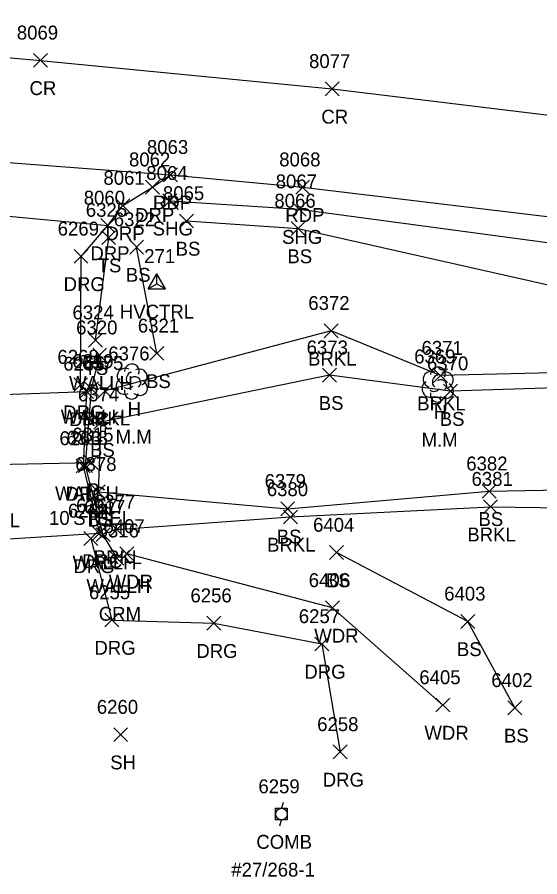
# Model space of a CAD drawing. Extents: x 1588028 to 1589597, y 137576 to 138176.
# Drawn here: x 1588699 to 1588774.4, y 137773.7 to 137897.5 of the extents above; entities that cross this region are included whole.
import ezdxf

# ---------------------------------------------------------------- set-up
doc = ezdxf.new("R2010")
doc.units = 0
for name, color, linetype in [('C_A', 7, 'Continuous'), ('C_I', 7, 'Continuous'), ('CPSM', 7, 'Continuous'), ('D_A', 7, 'Continuous'), ('D_C', 7, 'Continuous'), ('D_I', 7, 'Continuous'), ('D_TIC', 7, 'Continuous'), ('DCP', 7, 'Continuous'), ('DHW', 7, 'Continuous'), ('L_A', 7, 'Continuous'), ('L_C', 7, 'Continuous'), ('L_I', 7, 'Continuous'), ('L_TIC', 7, 'Continuous'), ('LAWA', 7, 'Continuous'), ('LAWE', 7, 'Continuous'), ('LELB', 7, 'Continuous'), ('LTD', 7, 'Continuous'), ('P_A', 7, 'Continuous'), ('P_I', 7, 'Continuous'), ('P_TIC', 7, 'Continuous'), ('PET', 7, 'Continuous'), ('PRC', 7, 'Continuous'), ('PSU', 7, 'Continuous'), ('R_A', 7, 'Continuous'), ('R_I', 7, 'Continuous'), ('R_TIC', 7, 'Continuous'), ('RDG', 7, 'Continuous'), ('RDP', 7, 'Continuous'), ('U_A', 7, 'Continuous'), ('U_C', 7, 'Continuous'), ('U_I', 7, 'Continuous'), ('UP', 7, 'Continuous')]:
    doc.layers.add(name, color=color, linetype=linetype)

msp = doc.modelspace()

# ---------------------------------------------------------------- linework, layer by layer
at = {"layer": 'CPSM'}
for p, q in [((1588717.9, 137858.35), (1588719.15, 137860.52)), ((1588720.4, 137858.35), (1588719.15, 137860.52)), ((1588719.15, 137859.07), (1588719.15, 137860.52)), ((1588717.9, 137858.35), (1588719.15, 137859.07)), ((1588719.15, 137859.07), (1588719.15, 137859.07)), ((1588719.15, 137859.07), (1588720.4, 137858.35)), ((1588717.9, 137858.35), (1588720.4, 137858.35))]:
    msp.add_line(p, q, dxfattribs=at)
at = {"layer": 'D_TIC'}
for points in [[(1588709.93, 137847.79), (1588711.93, 137849.79)], [(1588711.93, 137847.79), (1588709.93, 137849.79)], [(1588708.74, 137842.94), (1588710.74, 137844.94)], [(1588710.74, 137842.94), (1588708.74, 137844.94)], [(1588707.9, 137831.91), (1588709.9, 137833.91)], [(1588709.9, 137831.91), (1588707.9, 137833.91)], [(1588708.71, 137832.36), (1588710.71, 137834.36)], [(1588710.71, 137832.36), (1588708.71, 137834.36)], [(1588710.43, 137821.95), (1588712.43, 137823.95)], [(1588712.43, 137821.95), (1588710.43, 137823.95)], [(1588712.43, 137818.55), (1588714.43, 137820.55)], [(1588714.43, 137818.55), (1588712.43, 137820.55)]]:
    msp.add_lwpolyline(points, dxfattribs=at)
at = {"layer": 'DCP'}
msp.add_lwpolyline([(1588693.57, 137833.03), (1588709.71, 137833.36)], dxfattribs=at)
at = {"layer": 'DHW'}
msp.add_lwpolyline([(1588713.43, 137819.55), (1588711.43, 137822.95), (1588708.9, 137832.91), (1588709.74, 137843.94), (1588710.93, 137848.79)], dxfattribs=at)
at = {"layer": 'L_TIC'}
for points in [[(1588722.44, 137867.13), (1588724.44, 137869.13)], [(1588724.44, 137867.13), (1588722.44, 137869.13)], [(1588738.55, 137866.04), (1588740.55, 137868.04)], [(1588740.55, 137866.04), (1588738.55, 137868.04)], [(1588711.23, 137864.73), (1588713.23, 137866.73)], [(1588713.23, 137864.73), (1588711.23, 137866.73)], [(1588715.26, 137863.37), (1588717.26, 137865.37)], [(1588717.26, 137863.37), (1588715.26, 137865.37)], [(1588743.31, 137851.31), (1588745.31, 137853.31)], [(1588745.31, 137851.31), (1588743.31, 137853.31)], [(1588709.32, 137849.96), (1588711.32, 137851.96)], [(1588711.32, 137849.96), (1588709.32, 137851.96)], [(1588718.17, 137848.06), (1588720.17, 137850.06)], [(1588720.17, 137848.06), (1588718.17, 137850.06)], [(1588743.06, 137844.91), (1588745.06, 137846.91)], [(1588745.06, 137844.91), (1588743.06, 137846.91)], [(1588759.06, 137844.85), (1588761.06, 137846.85)], [(1588761.06, 137844.85), (1588759.06, 137846.85)], [(1588710.69, 137842.68), (1588712.69, 137844.68)], [(1588712.69, 137842.68), (1588710.69, 137844.68)], [(1588760.5, 137842.62), (1588762.5, 137844.62)], [(1588762.5, 137842.62), (1588760.5, 137844.62)], [(1588710.1, 137838.15), (1588712.1, 137840.15)], [(1588712.1, 137838.15), (1588710.1, 137840.15)], [(1588709.72, 137828.12), (1588711.72, 137830.12)], [(1588711.72, 137828.12), (1588709.72, 137830.12)], [(1588766.07, 137828.2), (1588768.07, 137830.2)], [(1588768.07, 137828.2), (1588766.07, 137830.2)], [(1588737.02, 137825.67), (1588739.02, 137827.67)], [(1588739.02, 137825.67), (1588737.02, 137827.67)], [(1588766.27, 137825.98), (1588768.27, 137827.98)], [(1588768.27, 137825.98), (1588766.27, 137827.98)], [(1588737.42, 137824.5), (1588739.42, 137826.5)], [(1588739.42, 137824.5), (1588737.42, 137826.5)], [(1588712.41, 137822.71), (1588714.41, 137824.71)], [(1588714.41, 137822.71), (1588712.41, 137824.71)], [(1588713.86, 137819.18), (1588715.86, 137821.18)], [(1588715.86, 137819.18), (1588713.86, 137821.18)], [(1588744.08, 137819.37), (1588746.08, 137821.37)], [(1588746.08, 137819.37), (1588744.08, 137821.37)], [(1588743.5, 137811.4), (1588745.5, 137813.4)], [(1588745.5, 137811.4), (1588743.5, 137813.4)], [(1588762.98, 137809.46), (1588764.98, 137811.46)], [(1588764.98, 137809.46), (1588762.98, 137811.46)], [(1588759.38, 137797.42), (1588761.38, 137799.42)], [(1588761.38, 137797.42), (1588759.38, 137799.42)], [(1588769.76, 137797), (1588771.76, 137799)], [(1588771.76, 137797), (1588769.76, 137799)], [(1588712.96, 137793.15), (1588714.96, 137795.15)], [(1588714.96, 137793.15), (1588712.96, 137795.15)]]:
    msp.add_lwpolyline(points, dxfattribs=at)
at = {"layer": 'LAWA'}
msp.add_lwpolyline([(1588760.38, 137798.42), (1588744.5, 137812.4), (1588714.86, 137820.18)], dxfattribs=at)
at = {"layer": 'LAWE'}
for points in [[(1588977.09, 137801.88), (1588949.99, 137800.55), (1588913.53, 137816.71), (1588888.44, 137827.65), (1588864.1, 137841.15), (1588838.93, 137847.71), (1588814.53, 137847.16), (1588788.4, 137846.57), (1588760.06, 137845.85), (1588744.31, 137852.31), (1588711.69, 137843.68)], [(1588713.41, 137823.71), (1588738.42, 137825.5), (1588767.27, 137826.98), (1588799.24, 137826.53), (1588827.86, 137827.03), (1588853.9, 137816.5), (1588892.67, 137800.6), (1588920.93, 137790.22), (1588953.81, 137785.34), (1588994.96, 137778.72)]]:
    msp.add_lwpolyline(points, dxfattribs=at)
at = {"layer": 'LELB'}
for points in [[(1588723.44, 137868.13), (1588739.55, 137867.04), (1588779.84, 137857.95)], [(1588710.32, 137850.96), (1588712.23, 137865.73)], [(1588719.17, 137849.06), (1588716.26, 137864.37)], [(1588976.95, 137800.76), (1588950.62, 137796.9), (1588914.44, 137812.1), (1588887.83, 137826.14), (1588862.59, 137838.68), (1588839.41, 137844.48), (1588814.28, 137844.58), (1588790.42, 137844.54), (1588761.5, 137843.62), (1588744.06, 137845.91), (1588711.1, 137839.15), (1588710.72, 137829.12), (1588738.02, 137826.67), (1588767.07, 137829.2), (1588800.85, 137829.84), (1588826.76, 137827.94), (1588856.44, 137818.62), (1588893.47, 137804.61), (1588923.15, 137792.66), (1588953.98, 137786.08), (1588988.16, 137786.33)], [(1588770.76, 137798), (1588763.98, 137810.46), (1588745.08, 137820.37)]]:
    msp.add_lwpolyline(points, dxfattribs=at)
at = {"layer": 'LTD'}
for p, q in [((1588715.53, 137845.05), (1588715.53, 137845.05)), ((1588715.53, 137845.05), (1588715.53, 137845.05)), ((1588759.63, 137844.62), (1588759.63, 137844.62)), ((1588759.63, 137844.62), (1588759.63, 137844.62))]:
    msp.add_line(p, q, dxfattribs=at)
for centre in [(1588715.58, 137846.48), (1588759.68, 137846.05)]:
    msp.add_arc(centre, 1.05, 335.5272, 180.9563, dxfattribs=at)
for centre, major_axis, ratio, start_param, end_param in [((1588714.74, 137845.72), (1.21, -0.51), 0.895232, 1.570796, 4.712389), ((1588715.32, 137845.51), (-0.208, -0.792), 0.645439, 3.141593, 6.283185), ((1588716.57, 137845.63), (-1.14, -0.48), 0.949671, 1.570796, 4.712389), ((1588758.84, 137845.28), (1.21, -0.51), 0.895232, 1.570796, 4.712389), ((1588760.68, 137845.2), (-1.14, -0.48), 0.949671, 1.570796, 4.712389), ((1588714.45, 137844.34), (0.58, -1.04), 0.959034, 3.141593, 6.283185), ((1588716.03, 137844.88), (-0.5, 0.667), 0.989748, 3.141593, 6.283185), ((1588716.53, 137844.22), (-1.09, 0.79), 0.841452, 1.570796, 4.712389), ((1588758.55, 137843.91), (0.58, -1.04), 0.959034, 3.141593, 6.283185), ((1588759.43, 137845.07), (-0.208, -0.792), 0.645439, 3.141593, 6.283185), ((1588760.13, 137844.45), (-0.5, 0.667), 0.989748, 3.141593, 6.283185), ((1588715.53, 137843.55), (0.26, 1.06), 0.942809, 1.570796, 4.712389), ((1588715.07, 137844.3), (-0.625, -0.083), 0.423636, 0, 3.141593), ((1588759.18, 137843.87), (-0.625, -0.083), 0.423636, 0, 3.141593), ((1588760.63, 137843.78), (-1.09, 0.79), 0.841452, 1.570796, 4.712389), ((1588759.63, 137843.12), (0.26, 1.06), 0.942809, 1.570796, 4.712389)]:
    msp.add_ellipse(centre, major_axis=major_axis, ratio=ratio, start_param=start_param, end_param=end_param, dxfattribs=at)
at = {"layer": 'P_TIC'}
for points in [[(1588701.39, 137890.26), (1588703.39, 137892.26)], [(1588703.39, 137890.26), (1588701.39, 137892.26)], [(1588743.44, 137886.15), (1588745.44, 137888.15)], [(1588745.44, 137886.15), (1588743.44, 137888.15)], [(1588720.13, 137873.78), (1588722.13, 137875.78)], [(1588722.13, 137873.78), (1588720.13, 137875.78)], [(1588739.19, 137871.99), (1588741.19, 137873.99)], [(1588741.19, 137871.99), (1588739.19, 137873.99)], [(1588720.03, 137870.04), (1588722.03, 137872.04)], [(1588722.03, 137870.04), (1588720.03, 137872.04)], [(1588738.68, 137868.83), (1588740.68, 137870.83)], [(1588740.68, 137868.83), (1588738.68, 137870.83)]]:
    msp.add_lwpolyline(points, dxfattribs=at)
at = {"layer": 'PET'}
msp.add_lwpolyline([(1588419.97, 137892.51), (1588466.09, 137889.91), (1588506.76, 137888.01), (1588548, 137885.78), (1588590.45, 137883.61), (1588638.45, 137880.69), (1588661.69, 137879.38), (1588677.51, 137878.09), (1588721.13, 137874.78), (1588740.19, 137872.99), (1588782.63, 137867.93), (1588820.21, 137862.87), (1588860.26, 137857.26), (1588914.01, 137849.9), (1588927.99, 137847.51)], dxfattribs=at)
at = {"layer": 'PRC'}
msp.add_lwpolyline([(1588420.99, 137907.2), (1588467.18, 137904.92), (1588507.29, 137903.21), (1588549.37, 137901.19), (1588590.55, 137899.3), (1588641.57, 137896.1), (1588661.53, 137894.88), (1588702.39, 137891.26), (1588744.44, 137887.15), (1588784.4, 137882.3), (1588823.71, 137877.3), (1588862.06, 137871.74), (1588917.24, 137863.85)], dxfattribs=at)
at = {"layer": 'PSU'}
msp.add_lwpolyline([(1588721.03, 137871.04), (1588739.68, 137869.83), (1588782.24, 137864.13), (1588819.87, 137858.36), (1588840.12, 137856.16)], dxfattribs=at)
at = {"layer": 'R_TIC'}
for points in [[(1588720.13, 137873.78), (1588722.13, 137875.78)], [(1588722.13, 137873.78), (1588720.13, 137875.78)], [(1588717.55, 137871.99), (1588719.55, 137873.99)], [(1588719.55, 137871.99), (1588717.55, 137873.99)], [(1588713.28, 137869.34), (1588715.28, 137871.34)], [(1588715.28, 137869.34), (1588713.28, 137871.34)], [(1588711.1, 137866.48), (1588713.1, 137868.48)], [(1588713.1, 137866.48), (1588711.1, 137868.48)], [(1588707.24, 137862.03), (1588709.24, 137864.03)], [(1588709.24, 137862.03), (1588707.24, 137864.03)], [(1588707.19, 137843.56), (1588709.19, 137845.56)], [(1588709.19, 137843.56), (1588707.19, 137845.56)], [(1588708.04, 137842.58), (1588710.04, 137844.58)], [(1588710.04, 137842.58), (1588708.04, 137844.58)], [(1588707.54, 137831.84), (1588709.54, 137833.84)], [(1588709.54, 137831.84), (1588707.54, 137833.84)], [(1588709.89, 137822.14), (1588711.89, 137824.14)], [(1588711.89, 137822.14), (1588709.89, 137824.14)], [(1588708.66, 137821.41), (1588710.66, 137823.41)], [(1588710.66, 137821.41), (1588708.66, 137823.41)], [(1588711.69, 137809.66), (1588713.69, 137811.66)], [(1588713.69, 137809.66), (1588711.69, 137811.66)], [(1588726.37, 137809.2), (1588728.37, 137811.2)], [(1588728.37, 137809.2), (1588726.37, 137811.2)], [(1588741.94, 137806.21), (1588743.94, 137808.21)], [(1588743.94, 137806.21), (1588741.94, 137808.21)], [(1588744.59, 137790.66), (1588746.59, 137792.66)], [(1588746.59, 137790.66), (1588744.59, 137792.66)]]:
    msp.add_lwpolyline(points, dxfattribs=at)
at = {"layer": 'RDG'}
for points in [[(1588708.24, 137863.03), (1588712.1, 137867.48)], [(1588708.19, 137844.56), (1588708.24, 137863.03)], [(1588709.66, 137822.41), (1588712.69, 137810.66), (1588727.37, 137810.2), (1588742.94, 137807.21), (1588745.59, 137791.66)]]:
    msp.add_lwpolyline(points, dxfattribs=at)
at = {"layer": 'RDP'}
for points in [[(1588677.51, 137878.09), (1588680.63, 137875.71), (1588683.24, 137873.49), (1588686.03, 137869.93), (1588712.1, 137867.48), (1588714.28, 137870.34), (1588718.55, 137872.99), (1588721.13, 137874.78)], [(1588693.95, 137822.08), (1588694.64, 137832.7), (1588693.86, 137838.68), (1588691.61, 137842.95), (1588709.04, 137843.58), (1588708.54, 137832.84), (1588710.89, 137823.14)], [(1588710.89, 137823.14), (1588693.95, 137822.08)]]:
    msp.add_lwpolyline(points, dxfattribs=at)
at = {"layer": 'UP'}
for p, q in [((1588737.38, 137784.37), (1588737.13, 137783.54)), ((1588736.29, 137781.87), (1588736.29, 137783.54)), ((1588736.29, 137783.54), (1588737.96, 137783.54)), ((1588737.96, 137783.54), (1588737.96, 137781.87)), ((1588737.96, 137781.87), (1588736.29, 137781.87)), ((1588736.88, 137781.04), (1588737.13, 137781.87)), ((1588737.13, 137782.71), (1588737.13, 137782.71))]:
    msp.add_line(p, q, dxfattribs=at)
msp.add_circle((1588737.13, 137782.71), 0.833, dxfattribs=at)

# ---------------------------------------------------------------- texts
at = {"layer": 'C_A'}
msp.add_text('HVCTRL', height=2, dxfattribs=at).set_placement((1588713.84, 137854.07))
at = {"layer": 'C_I'}
msp.add_text('271', height=2, dxfattribs=at).set_placement((1588717.35, 137862.07))
at = {"layer": 'D_A'}
for s, p in [('WALLH', (1588706.52, 137843.79)), ('WALLH', (1588705.33, 137838.94)), ('P', (1588709.09, 137828.36)), ('WALLH', (1588704.5, 137827.91)), ('WALLH', (1588707.02, 137817.95)), ('WALLH', (1588709.02, 137814.55))]:
    msp.add_text(s, height=2, dxfattribs=at).set_placement(p)
at = {"layer": 'D_C'}
for s, p in [("10'STEEL", (1588703.63, 137824.36)), ("10'STEEL", (1588687.49, 137824.03)), ('CRM', (1588710.8, 137810.55))]:
    msp.add_text(s, height=2, dxfattribs=at).set_placement(p)
at = {"layer": 'D_I'}
for s, p in [('6320', (1588707.54, 137851.79)), ('6319', (1588706.99, 137846.94)), ('6318', (1588706.16, 137835.91)), ('6315', (1588706.97, 137836.36)), ('6317', (1588708.69, 137825.95)), ('6316', (1588710.64, 137822.55))]:
    msp.add_text(s, height=2, dxfattribs=at).set_placement(p)
at = {"layer": 'L_A'}
for s, p in [('BS', (1588721.88, 137863.13)), ('BS', (1588737.99, 137862.04)), ('TS', (1588710.64, 137860.73)), ('BS', (1588714.7, 137859.37)), ('BRKL', (1588740.96, 137847.31)), ('TS', (1588708.73, 137845.96)), ('BS', (1588717.61, 137844.06)), ('BS', (1588742.5, 137840.91)), ('BRKL', (1588756.7, 137840.85)), ('H', (1588714.96, 137840.05)), ('H', (1588759.07, 137839.62)), ('BRKL', (1588708.34, 137838.68)), ('BS', (1588759.94, 137838.62)), ('BS', (1588709.54, 137834.15)), ('BS', (1588709.16, 137824.12)), ('BS', (1588765.52, 137824.2)), ('BRKL', (1588763.92, 137821.98)), ('BS', (1588736.46, 137821.67)), ('BRKL', (1588735.06, 137820.5)), ('BRKL', (1588710.06, 137818.71)), ('WDR', (1588712.23, 137815.18)), ('BS', (1588743.52, 137815.37)), ('WDR', (1588741.86, 137807.4)), ('BS', (1588762.42, 137805.46)), ('WDR', (1588757.74, 137793.42)), ('BS', (1588769.2, 137793)), ('SH', (1588712.45, 137789.15))]:
    msp.add_text(s, height=2, dxfattribs=at).set_placement(p)
at = {"layer": 'L_C'}
for p in [(1588713.23, 137836.05), (1588757.33, 137835.62)]:
    msp.add_text('M.M', height=2, dxfattribs=at).set_placement(p)
at = {"layer": 'L_I'}
for s, p in [('8065', (1588720.05, 137871.13)), ('8066', (1588736.11, 137870.04)), ('6325', (1588708.93, 137868.73)), ('6322', (1588712.96, 137867.37)), ('6372', (1588741, 137855.31)), ('6324', (1588707.01, 137853.96)), ('6321', (1588716.43, 137852.06)), ('6376', (1588712.17, 137848.05)), ('6373', (1588740.76, 137848.91)), ('6371', (1588757.32, 137848.85)), ('6375', (1588708.39, 137846.68)), ('6369', (1588756.27, 137847.62)), ('6370', (1588758.11, 137846.62)), ('6374', (1588707.79, 137842.15)), ('6378', (1588707.41, 137832.12)), ('6382', (1588763.77, 137832.2)), ('6379', (1588734.71, 137829.67)), ('6381', (1588764.53, 137829.98)), ('6380', (1588735.02, 137828.5)), ('6377', (1588710.1, 137826.71)), ('6407', (1588711.48, 137823.18)), ('6404', (1588741.69, 137823.37)), ('6406', (1588741.06, 137815.4)), ('6403', (1588760.59, 137813.46)), ('6405', (1588757, 137801.42)), ('6402', (1588767.38, 137801)), ('6260', (1588710.52, 137797.15))]:
    msp.add_text(s, height=2, dxfattribs=at).set_placement(p)
at = {"layer": 'P_A'}
for s, p in [('CR', (1588700.82, 137886.26)), ('CR', (1588742.88, 137882.15)), ('RDP', (1588718.61, 137869.78)), ('RDP', (1588737.68, 137867.99)), ('SHG', (1588718.57, 137866.04)), ('SHG', (1588737.22, 137864.83))]:
    msp.add_text(s, height=2, dxfattribs=at).set_placement(p)
at = {"layer": 'P_I'}
for s, p in [('8069', (1588698.99, 137894.26)), ('8077', (1588741.11, 137890.15)), ('8063', (1588717.74, 137877.78)), ('8068', (1588736.81, 137875.99)), ('8064', (1588717.65, 137874.04)), ('8067', (1588736.3, 137872.83))]:
    msp.add_text(s, height=2, dxfattribs=at).set_placement(p)
at = {"layer": 'R_A'}
for s, p in [('DRP', (1588718.61, 137869.78)), ('DRP', (1588716.04, 137867.99)), ('DRP', (1588711.77, 137865.34)), ('DRP', (1588709.59, 137862.48)), ('DRG', (1588705.73, 137858.03)), ('DRG', (1588705.68, 137839.56)), ('DRC', (1588706.53, 137838.58)), ('DRC', (1588706.02, 137827.84)), ('DRC', (1588708.38, 137818.14)), ('DRG', (1588707.15, 137817.41)), ('DRG', (1588710.17, 137805.66)), ('DRG', (1588724.86, 137805.2)), ('DRG', (1588740.43, 137802.21)), ('DRG', (1588743.08, 137786.66))]:
    msp.add_text(s, height=2, dxfattribs=at).set_placement(p)
at = {"layer": 'R_I'}
for s, p in [('8063', (1588717.74, 137877.78)), ('8062', (1588715.16, 137875.99)), ('8061', (1588711.47, 137873.34)), ('8060', (1588708.63, 137870.48)), ('6269', (1588704.88, 137866.03)), ('6268', (1588704.84, 137847.56)), ('6265', (1588705.68, 137846.58)), ('6266', (1588705.13, 137835.84)), ('6267', (1588707.53, 137826.14)), ('6254', (1588706.35, 137825.41)), ('6255', (1588709.38, 137813.66)), ('6256', (1588724.01, 137813.2)), ('6257', (1588739.63, 137810.21)), ('6258', (1588742.28, 137794.66))]:
    msp.add_text(s, height=2, dxfattribs=at).set_placement(p)
at = {"layer": 'U_A'}
msp.add_text('COMB', height=2, dxfattribs=at).set_placement((1588733.51, 137777.71))
at = {"layer": 'U_C'}
msp.add_text('#27/268-1', height=2, dxfattribs=at).set_placement((1588729.9, 137773.71))
at = {"layer": 'U_I'}
msp.add_text('6259', height=2, dxfattribs=at).set_placement((1588733.81, 137785.71))

doc.saveas('drawing.dxf')
